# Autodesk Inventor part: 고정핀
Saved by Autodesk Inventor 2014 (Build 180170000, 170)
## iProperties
Created: 2025-02
Part Number: 고정핀
Material: 일반
Document SubType Name: Modeling
Designer: dg
Density: 1 g/cm^3
Appearance: 기본값
Author: dg
Author: jhkim
Creation Date: 2025-02-05
Sending System: Autodesk Inventor 2025
Preprocessor: ST-DEVELOPER v20
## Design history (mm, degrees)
node "고정핀1"
node "솔리드1"
node "기준1"
